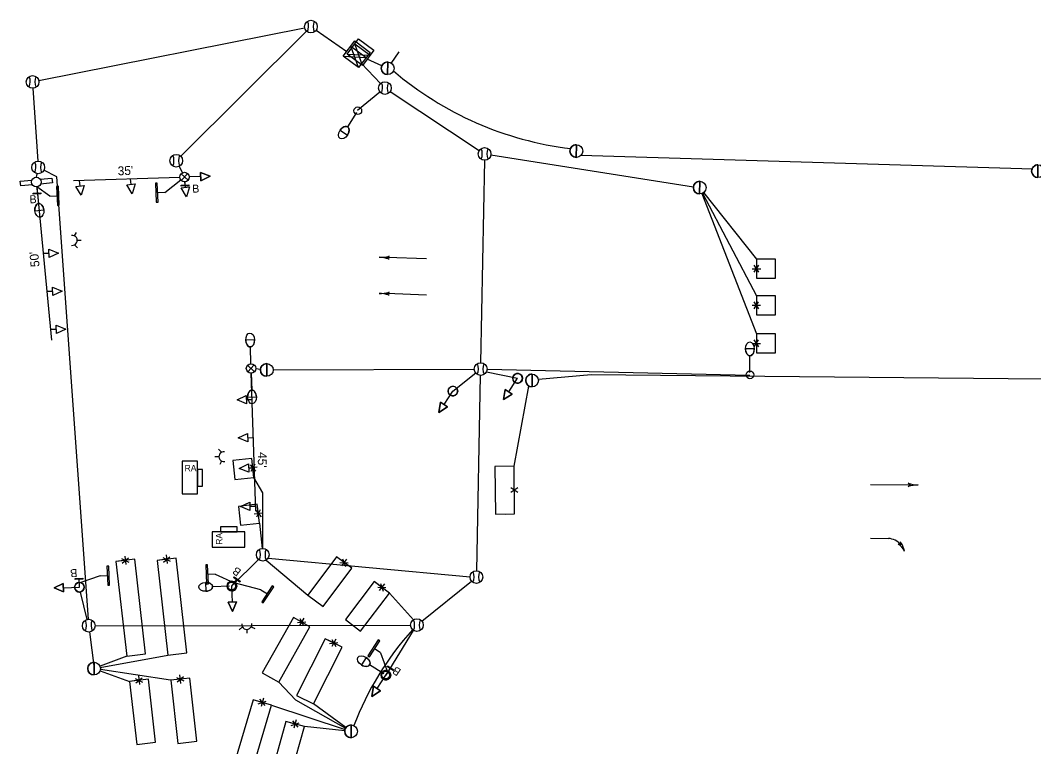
# Model space of a CAD drawing. Extents: x 596176 to 605330, y 332416 to 402398.
# Drawn here: x 604310.9 to 604629.8, y 339247.6 to 339476.3 of the extents above; entities that cross this region are included whole.
import ezdxf

# ---------------------------------------------------------------- set-up
doc = ezdxf.new("R2010")
doc.units = 0
for name, color, linetype in [('P_LTG', 7, 'Continuous'), ('P_SIG', 7, 'Continuous'), ('P_SIG_Bold', 7, 'Continuous'), ('P_SIG_Conduit', 7, 'Continuous'), ('P_SIG_IC', 7, 'Continuous'), ('P_SIG_Loops', 7, 'Continuous')]:
    doc.layers.add(name, color=color, linetype=linetype)

# ---------------------------------------------------------------- blocks, each defined once
blk = doc.blocks.new('_U321')
at = {"layer": 'P_LTG'}
for p, q in [((4.32, 25.12), (-4.14, 25.12)), ((0.05, 2.3), (0.05, 18.44))]:
    blk.add_line(p, q, dxfattribs=at)
blk.add_circle((0.05, 0.15), 3.68, dxfattribs=at)
blk.add_ellipse((0.09, 25.12), major_axis=(0, 6.65), ratio=0.636439, dxfattribs=at)
blk.add_ellipse((0.09, 25.12), major_axis=(0, 6.65), ratio=0.636439, start_param=1.570796, end_param=4.712389, dxfattribs=at)
blk = doc.blocks.new('_U322')
at = {"layer": 'P_LTG'}
for p, q in [((4.32, 25.12), (-4.14, 25.12)), ((0.05, 2.3), (0.05, 18.44))]:
    blk.add_line(p, q, dxfattribs=at)
blk.add_ellipse((0.09, 25.12), major_axis=(0, 6.65), ratio=0.636439, dxfattribs=at)
blk.add_ellipse((0.09, 25.12), major_axis=(0, 6.65), ratio=0.636439, start_param=1.570796, end_param=4.712389, dxfattribs=at)
blk = doc.blocks.new('_U226')
at = {"layer": 'P_SIG'}
blk.add_line((0.03, 6.11), (-0.03, -6.09), dxfattribs=at)
blk.add_lwpolyline([(-0.03, -6.09), (0.03, 6.11)], dxfattribs=at)
blk.add_circle((0, 0.01), 6.1, dxfattribs=at)
for start, end in [(89.70079, 180), (180, 269.70079)]:
    blk.add_arc((0, 0.01), 6.1, start, end, dxfattribs=at)
blk = doc.blocks.new('_U307')
at = {"layer": 'P_SIG_Loops'}
for p, q in [((0, 0), (0, -0.229)), ((0.467, -0.23), (0.671, -0.23)), ((0.517, -0.313), (0.624, -0.147)), ((0.627, -0.312), (0.518, -0.146))]:
    blk.add_line(p, q, dxfattribs=at)
blk.add_lwpolyline([(0, -0.229), (1.143, -0.229), (1.143, 0.229), (0, 0.229)], close=True, dxfattribs=at)
blk = doc.blocks.new('_U319')
at = {"layer": 'P_SIG'}
for p, q in [((-0.675, 0.115), (-0.743, 0.129)), ((-0.725, 0.057), (-0.743, 0.129)), ((-0.017, -0.02), (-0.443, -0.02))]:
    blk.add_line(p, q, dxfattribs=at)
for centre, radius, start, end in [((-0.479, 0.454), 0.392, 205.2667, 239.9151), ((-0.377, 0.361), 0.462, 189.3153, 221.1715), ((-0.412, 0.421), 0.442, 221.4708, 266.0347)]:
    blk.add_arc(centre, radius, start, end, dxfattribs=at)
blk = doc.blocks.new('_U318')
at = {"layer": 'P_SIG'}
blk.add_line((-0.017, -0.02), (-0.975, -0.02), dxfattribs=at)
blk.add_lwpolyline([(-0.914, 0.018), (-0.975, -0.02), (-0.914, -0.058)], dxfattribs=at)
for centre, start, end in [((-1.158, 0.78), 270, 287.7623), ((-1.158, -0.819), 72.2377, 90)]:
    blk.add_arc(centre, 0.799, start, end, dxfattribs=at)
blk = doc.blocks.new('CONTROL CABINET_2')
at = {"layer": 'P_SIG'}
for p, q in [((-0.229, 0.305), (0.229, 0.305)), ((-0.229, -0.152), (-0.229, 0.305)), ((0.229, 0.305), (0.229, -0.152)), ((-0.229, 0.152), (0.229, 0.152)), ((-0.229, -0.152), (0.229, 0.152)), ((0.229, -0.152), (-0.229, 0.152)), ((0.229, -0.152), (-0.229, -0.152))]:
    blk.add_line(p, q, dxfattribs=at)

msp = doc.modelspace()

# ---------------------------------------------------------------- linework, layer by layer
at = {"layer": 'P_SIG'}
for p, q in [((604412.53, 339465.01), (604416.12, 339469.82)), ((604416.12, 339469.82), (604420.93, 339466.23)), ((604414.93, 339468.21), (604419.74, 339464.63)), ((604417.34, 339461.42), (604414.93, 339468.21)), ((604417.34, 339461.42), (604412.53, 339465.01)), ((604412.53, 339465.01), (604419.74, 339464.63)), ((604420.93, 339466.23), (604417.34, 339461.42)), ((604329.66, 339424.14), (604329.45, 339425.9)), ((604345.71, 339424.66), (604345.5, 339426.42)), ((604356.38, 339422.11), (604361.38, 339426.04)), ((604362.84, 339423.71), (604362.63, 339425.47)), ((604362.63, 339425.46), (604362.67, 339424.47)), ((604367.61, 339427.11), (604364.06, 339427.01)), ((604524.7, 339425.64), (604524.68, 339421.64)), ((604316.05, 339423.89), (604316.14, 339421.91)), ((604320.12, 339420.97), (604316.11, 339423.9)), ((604356.38, 339422.11), (604353.98, 339422)), ((604320.12, 339420.97), (604322.52, 339421.08)), ((604327.93, 339408.43), (604328.5, 339409.52)), ((604328.77, 339407.07), (604330, 339407.09)), ((604319.9, 339402.91), (604318.13, 339402.86)), ((604327.95, 339405.64), (604328.85, 339404.67)), ((604438.73, 339401.16), (604426.17, 339401.61)), ((604321.06, 339390.95), (604319.29, 339390.89)), ((604438.73, 339389.81), (604426.17, 339390.25)), ((604322.22, 339378.98), (604320.45, 339378.92)), ((604388.46, 339368.23), (604388.44, 339364.23)), ((604464.6, 339359.35), (604467.38, 339363.58)), ((604444.23, 339355.34), (604447.01, 339359.56)), ((604382.04, 339356.89), (604383.81, 339356.94)), ((604382.43, 339344.89), (604384.2, 339344.95)), ((604373.36, 339338.87), (604372.14, 339338.84)), ((604374.19, 339340.3), (604373.29, 339341.27)), ((604374.21, 339337.5), (604373.64, 339336.42)), ((604382.73, 339335.32), (604384.5, 339335.37)), ((604383.1, 339323.28), (604384.87, 339323.34)), ((604335.97, 339301.38), (604329.33, 339299.05)), ((604335.97, 339301.38), (604338.37, 339301.5)), ((604372.22, 339301.9), (604369.82, 339301.79)), ((604372.22, 339301.9), (604378.2, 339299.14)), ((604324.42, 339297.65), (604329.48, 339297.8)), ((604329.48, 339297.77), (604329.34, 339300.27)), ((604377.45, 339298.14), (604378.95, 339300.14)), ((604377.6, 339293.11), (604377.45, 339298.16)), ((604386.61, 339296.99), (604378.2, 339299.14)), ((604386.61, 339296.99), (604388.62, 339295.68)), ((604380.75, 339285.33), (604379.78, 339284.43)), ((604382.18, 339284.51), (604382.2, 339283.28)), ((604383.54, 339285.35), (604384.63, 339284.78)), ((604424.25, 339277.16), (604422.23, 339278.46)), ((604424.25, 339277.16), (604426.55, 339270.89)), ((604334.1, 339274.17), (604334.08, 339270.17)), ((604425.9, 339270.07), (604427.28, 339272.15)), ((604423.13, 339265.87), (604425.91, 339270.09)), ((604414.98, 339254.42), (604414.96, 339250.42))]:
    msp.add_line(p, q, dxfattribs=at)
for points in [[(604370.57, 339427.2), (604367.65, 339425.79), (604367.57, 339428.43), (604370.57, 339427.2)], [(604370.57, 339427.2), (604367.65, 339425.79), (604367.57, 339428.43), (604370.57, 339427.2)], [(604367.57, 339428.43), (604367.65, 339425.79), (604370.57, 339427.2), (604367.57, 339428.43)], [(604524.68, 339421.64), (604524.7, 339425.64)], [(604426.98, 339402.08), (604426.17, 339401.61), (604426.95, 339401.08)], [(604426.98, 339390.72), (604426.17, 339390.25), (604426.95, 339389.73)], [(604388.44, 339364.23), (604388.46, 339368.23)], [(604462.99, 339356.88), (604463.5, 339360.07), (604465.71, 339358.63), (604462.99, 339356.88)], [(604463.5, 339360.07), (604462.99, 339356.88), (604465.71, 339358.63), (604463.5, 339360.07)], [(604442.61, 339352.86), (604443.13, 339356.06), (604445.33, 339354.61), (604442.61, 339352.86)], [(604443.13, 339356.06), (604442.61, 339352.86), (604445.33, 339354.61), (604443.13, 339356.06)], [(604321.47, 339297.56), (604324.38, 339298.97), (604324.47, 339296.33), (604321.47, 339297.56)], [(604324.38, 339298.97), (604321.47, 339297.56), (604324.47, 339296.33), (604324.38, 339298.97)], [(604377.69, 339290.15), (604376.28, 339293.07), (604378.92, 339293.15), (604377.69, 339290.15)], [(604376.28, 339293.07), (604377.69, 339290.15), (604378.92, 339293.15), (604376.28, 339293.07)], [(604334.08, 339270.17), (604334.1, 339274.17)], [(604421.52, 339263.39), (604422.03, 339266.59), (604424.24, 339265.15), (604421.52, 339263.39)], [(604422.03, 339266.59), (604421.52, 339263.39), (604424.24, 339265.15), (604422.03, 339266.59)], [(604414.96, 339250.42), (604414.98, 339254.42)]]:
    msp.add_lwpolyline(points, dxfattribs=at)
for points in [[(604346.06, 339421.72), (604344.41, 339424.5), (604347.02, 339424.81)], [(604354.25, 339419.05), (604353.97, 339425.04), (604353.37, 339425.01), (604353.65, 339419.02)], [(604314.94, 339421.86), (604317.34, 339421.97), (604317.35, 339421.64), (604314.95, 339421.53)], [(604322.24, 339424.03), (604322.52, 339418.03), (604323.12, 339418.06), (604322.84, 339424.06)], [(604330.01, 339421.21), (604328.36, 339423.99), (604330.97, 339424.3)], [(604361.47, 339424.41), (604363.87, 339424.52), (604363.89, 339424.2), (604361.49, 339424.09)], [(604363.19, 339420.77), (604361.53, 339423.55), (604364.14, 339423.86)], [(604322.86, 339403.01), (604319.94, 339401.6), (604319.86, 339404.23)], [(604324.02, 339391.04), (604321.1, 339389.63), (604321.02, 339392.26)], [(604325.17, 339379.07), (604322.26, 339377.66), (604322.17, 339380.29)], [(604379.09, 339356.79), (604382, 339358.2), (604382.08, 339355.57)], [(604379.47, 339344.8), (604382.39, 339346.21), (604382.47, 339343.58)], [(604366.6, 339327.17), (604366.6, 339337.52), (604361.78, 339337.52), (604361.78, 339327.17)], [(604379.78, 339335.22), (604382.69, 339336.63), (604382.78, 339334)], [(604368.23, 339334.89), (604366.63, 339334.89), (604366.63, 339329.62), (604368.23, 339329.62)], [(604380.15, 339323.19), (604383.06, 339324.6), (604383.15, 339321.97)], [(604373.85, 339316.83), (604373.85, 339315.23), (604379.12, 339315.23), (604379.12, 339316.83)], [(604381.57, 339315.2), (604371.23, 339315.2), (604371.23, 339310.37), (604381.57, 339310.37)], [(604338.1, 339304.44), (604338.38, 339298.45), (604338.98, 339298.48), (604338.7, 339304.47)], [(604370.09, 339298.84), (604369.82, 339304.84), (604369.22, 339304.81), (604369.49, 339298.81)], [(604330.54, 339300.34), (604328.14, 339300.2), (604328.12, 339300.52), (604330.52, 339300.66)], [(604379.91, 339299.43), (604377.99, 339300.86), (604378.18, 339301.12), (604380.1, 339299.69)], [(604390.12, 339298.23), (604386.84, 339293.2), (604387.34, 339292.88), (604390.62, 339297.9)], [(604420.74, 339275.91), (604424, 339280.95), (604423.49, 339281.27), (604420.24, 339276.23)], [(604428.28, 339271.49), (604426.28, 339272.82), (604426.46, 339273.09), (604428.46, 339271.76)]]:
    msp.add_lwpolyline(points, close=True, dxfattribs=at)
for centre, radius in [((604402.31, 339474.34), 2), ((604314.71, 339456.92), 2), ((604425.6, 339454.98), 2), ((604456.98, 339434.26), 2), ((604316.49, 339430), 2), ((604359.94, 339432.11), 2), ((604524.69, 339423.64), 2), ((604388.45, 339366.23), 2), ((604455.76, 339366.51), 2), ((604467.38, 339363.58), 1.52), ((604467.38, 339363.58), 1.52), ((604467.38, 339363.58), 1.52), ((604447.01, 339359.56), 1.52), ((604447.01, 339359.56), 1.52), ((604447.01, 339359.56), 1.52), ((604387.17, 339308.02), 2), ((604454.4, 339301), 2), ((604329.48, 339297.8), 1.52), ((604329.48, 339297.8), 1.52), ((604329.48, 339297.8), 1.52), ((604377.45, 339298.16), 1.52), ((604377.45, 339298.16), 1.52), ((604377.45, 339298.16), 1.52), ((604332.42, 339285.69), 2), ((604435.69, 339285.86), 2), ((604334.09, 339272.17), 2), ((604425.91, 339270.09), 1.52), ((604425.91, 339270.09), 1.52), ((604425.91, 339270.09), 1.52), ((604414.97, 339252.42), 2)]:
    msp.add_circle(centre, radius, dxfattribs=at)
for centre, radius, start, end in [((604397.24, 339474.37), 4.36, 336.6741, 22.5272), ((604407.38, 339474.38), 4.36, 157.5751, 203.4282), ((604309.64, 339456.95), 4.36, 336.6741, 22.5272), ((604319.78, 339456.96), 4.36, 157.5751, 203.4282), ((604420.53, 339455.01), 4.36, 336.6741, 22.5272), ((604430.67, 339455.02), 4.36, 157.5751, 203.4282), ((604451.91, 339434.29), 4.36, 336.6741, 22.5272), ((604462.05, 339434.3), 4.36, 157.5751, 203.4282), ((604311.42, 339430.03), 4.36, 336.6741, 22.5272), ((604321.56, 339430.04), 4.36, 157.5751, 203.4282), ((604354.87, 339432.14), 4.36, 336.6741, 22.5272), ((604365.01, 339432.15), 4.36, 157.5751, 203.4282), ((604524.69, 339423.64), 2, 89.7008, 180), ((604524.69, 339423.64), 2, 180, 269.7008), ((604327.2, 339407.03), 1.58, 263.3712, 98.8787), ((604424.14, 339412.17), 10.49, 267.9585, 285.7208), ((604423.39, 339391.21), 10.49, 70.1962, 87.9585), ((604424.14, 339400.82), 10.49, 267.9585, 285.7208), ((604423.39, 339379.86), 10.49, 70.1962, 87.9585), ((604388.45, 339366.23), 2, 89.7008, 180), ((604450.69, 339366.54), 4.36, 336.6741, 22.5272), ((604460.83, 339366.55), 4.36, 157.5751, 203.4282), ((604388.45, 339366.23), 2, 180, 269.7008), ((604467.38, 339363.58), 1.52, 56.8293, 236.8293), ((604467.38, 339363.58), 1.52, 236.8293, 56.8293), ((604447.01, 339359.56), 1.52, 56.8293, 236.8293), ((604447.01, 339359.56), 1.52, 236.8293, 56.8293), ((604374.94, 339338.91), 1.58, 83.3712, 278.8787), ((604382.1, 339308.06), 4.36, 336.6741, 22.5272), ((604392.24, 339308.07), 4.36, 157.5751, 203.4282), ((604449.33, 339301.04), 4.36, 336.6741, 22.5272), ((604459.47, 339301.05), 4.36, 157.5751, 203.4282), ((604329.48, 339297.8), 1.52, 1.8031, 181.8031), ((604329.48, 339297.8), 1.52, 181.8031, 1.8031), ((604377.45, 339298.16), 1.52, 91.8031, 271.8031), ((604377.45, 339298.16), 1.52, 271.8031, 91.8031), ((604327.35, 339285.73), 4.36, 336.6741, 22.5272), ((604337.49, 339285.73), 4.36, 157.5751, 203.4282), ((604382.14, 339286.08), 1.58, 173.3712, 8.8787), ((604430.62, 339285.9), 4.36, 336.6741, 22.5272), ((604440.76, 339285.9), 4.36, 157.5751, 203.4282), ((604334.09, 339272.17), 2, 89.7008, 180), ((604334.09, 339272.17), 2, 180, 269.7008), ((604425.91, 339270.09), 1.52, 56.8293, 236.8293), ((604425.91, 339270.09), 1.52, 236.8293, 56.8293), ((604414.97, 339252.42), 2, 89.7008, 180), ((604414.97, 339252.42), 2, 180, 269.7008)]:
    msp.add_arc(centre, radius, start, end, dxfattribs=at)
at = {"layer": 'P_SIG_Bold'}
for p, q in [((604363.58, 339428.06), (604361.53, 339425.87)), ((604327.58, 339425.84), (604361.06, 339426.92)), ((604361.46, 339427.99), (604363.65, 339425.94)), ((604316.05, 339423.89), (604320.71, 339375.62)), ((604382.4, 339367.72), (604384.59, 339365.66)), ((604382.47, 339365.6), (604384.52, 339367.78)), ((604384.94, 339321.71), (604383.55, 339365.19))]:
    msp.add_line(p, q, dxfattribs=at)
for points in [[(604314.68, 339424.51), (604311, 339424.16), (604310.85, 339425.65), (604314.54, 339426.01)], [(604317.12, 339426.26), (604320.81, 339426.61), (604320.95, 339425.12), (604317.27, 339424.76)]]:
    msp.add_lwpolyline(points, dxfattribs=at)
for centre in [(604362.56, 339426.96), (604315.9, 339425.39), (604383.5, 339366.69)]:
    msp.add_circle(centre, 1.5, dxfattribs=at)
at = {"layer": 'P_SIG_Conduit'}
for p, q in [((604316.66, 339457.36), (604400.34, 339473.95)), ((604361.35, 339433.52), (604400.89, 339472.93)), ((604403.95, 339473.2), (604413.66, 339466.52)), ((604314.84, 339454.92), (604316.36, 339431.99)), ((604424.05, 339453.71), (604416.97, 339447.87)), ((604427.27, 339453.88), (604455.31, 339435.36)), ((604456.94, 339432.26), (604455.71, 339368.51)), ((604316, 339426.88), (604316.17, 339428.02)), ((604360.84, 339430.33), (604361.88, 339428.3)), ((604455.63, 339364.51), (604454.44, 339303)), ((604457.76, 339366.47), (604540.44, 339364.59)), ((604377.45, 339298.19), (604385.87, 339306.5)), ((604437.26, 339287.1), (604452.84, 339299.74)), ((604329.66, 339296.29), (604331.85, 339287.61)), ((604334.42, 339285.68), (604433.69, 339285.83)), ((604332.67, 339283.71), (604334.09, 339272.17))]:
    msp.add_line(p, q, dxfattribs=at)
for points in [[(604418.3, 339462.7), (604424.22, 339456.43)], [(604458.96, 339433.95), (604522.77, 339423.92)], [(604332.28, 339287.69), (604322.39, 339427.06), (604318.27, 339429.09)], [(604386.46, 339366.41), (604384.99, 339366.55)], [(604390.45, 339366.23), (604453.76, 339366.5)], [(604447.01, 339359.56), (604454.2, 339365.26)], [(604457.57, 339365.64), (604467.38, 339363.58)], [(604632.71, 339363.27), (604490.54, 339364.68), (604473.91, 339363.18)], [(604388.85, 339306.94), (604452.4, 339301.03)], [(604425.97, 339270.06), (604434.61, 339284.18)]]:
    msp.add_lwpolyline(points, dxfattribs=at)
msp.add_arc((604504.2, 339220.92), 94.4, 137.747, 159.353, dxfattribs=at)
at = {"layer": 'P_SIG_IC'}
for points in [[(604429.97, 339466.41), (604427.45, 339462.73)], [(604424.64, 339462.02), (604420.01, 339464.05)], [(604629.49, 339429.46), (604487.32, 339433.76)]]:
    msp.add_lwpolyline(points, dxfattribs=at)
msp.add_arc((604496.64, 339540.36), 105.18, 229.479, 263.1167, dxfattribs=at)
at = {"layer": 'P_SIG_Loops'}
for p, q in [((604525.41, 339421.77), (604542.53, 339377.59)), ((604525.62, 339421.87), (604542.53, 339389.6)), ((604525.93, 339422.07), (604542.57, 339401.1)), ((604541.2, 339398.08), (604543.88, 339398.09)), ((604541.85, 339397), (604543.26, 339399.17)), ((604543.31, 339397.01), (604541.88, 339399.18)), ((604542.57, 339398.1), (604542.58, 339395.1)), ((604541.16, 339386.58), (604543.84, 339386.58)), ((604541.81, 339385.49), (604543.22, 339387.67)), ((604543.27, 339385.51), (604541.83, 339387.68)), ((604542.53, 339386.6), (604542.53, 339383.6)), ((604541.16, 339374.57), (604543.84, 339374.58)), ((604541.81, 339373.49), (604543.22, 339375.66)), ((604543.27, 339373.5), (604541.83, 339375.67)), ((604542.53, 339374.59), (604542.53, 339371.59)), ((604466.26, 339335.87), (604470.95, 339361.15)), ((604385.4, 339335.56), (604382.74, 339335.25)), ((604383.18, 339336.39), (604384.85, 339334.39)), ((604384.63, 339336.56), (604383.47, 339334.24)), ((604384.04, 339335.38), (604383.7, 339338.36)), ((604385.8, 339320.95), (604385.46, 339323.93)), ((604387.17, 339321.12), (604384.5, 339320.82)), ((604384.95, 339321.95), (604386.62, 339319.96)), ((604386.39, 339322.13), (604385.24, 339319.81)), ((604342.75, 339306.84), (604345.07, 339305.69)), ((604342.92, 339305.4), (604344.92, 339307.06)), ((604343.75, 339307.61), (604344.06, 339304.95)), ((604355.73, 339307.18), (604358.05, 339306.03)), ((604355.91, 339305.73), (604357.9, 339307.4)), ((604356.74, 339307.95), (604357.04, 339305.29)), ((604412.75, 339305.55), (604410.34, 339307.33)), ((604343.93, 339306.25), (604340.95, 339305.91)), ((604356.91, 339306.59), (604353.93, 339306.25)), ((604388.24, 339306.34), (604401.41, 339295.28)), ((604411.44, 339305.61), (604414.03, 339305.47)), ((604413.55, 339306.66), (604411.96, 339304.51)), ((604412.29, 339306.78), (604413.2, 339304.36)), ((604424.65, 339297.76), (604422.26, 339299.57)), ((604423.34, 339297.83), (604425.93, 339297.66)), ((604425.47, 339298.86), (604423.85, 339296.73)), ((604424.21, 339299), (604425.09, 339296.56)), ((604427.04, 339295.94), (604434.64, 339287.57)), ((604399.43, 339286.83), (604396.81, 339288.3)), ((604400.08, 339288.03), (604398.77, 339285.7)), ((604398.82, 339288), (604400.02, 339285.7)), ((604398.12, 339286.72), (604400.71, 339286.91)), ((604409.52, 339280.24), (604406.84, 339281.59)), ((604408.86, 339281.38), (604410.16, 339279.14)), ((604410.12, 339281.47), (604408.92, 339279.08)), ((604408.21, 339280.08), (604410.8, 339280.38)), ((604344.35, 339276.1), (604335.95, 339272.91)), ((604336.05, 339272.55), (604357.33, 339276.44)), ((604358.12, 339268.48), (604336.07, 339271.86)), ((604335.97, 339271.49), (604345.23, 339268.15)), ((604347.03, 339269.08), (604349.35, 339267.93)), ((604347.2, 339267.64), (604349.2, 339269.31)), ((604348.03, 339269.85), (604348.34, 339267.19)), ((604361.19, 339268.83), (604358.21, 339268.49)), ((604360.01, 339269.42), (604362.33, 339268.27)), ((604360.19, 339267.98), (604362.19, 339269.64)), ((604361.02, 339270.19), (604361.32, 339267.53)), ((604348.21, 339268.49), (604345.23, 339268.15)), ((604387.01, 339261.51), (604384.13, 339262.36)), ((604386.15, 339262.51), (604387.84, 339260.55)), ((604387.38, 339262.83), (604386.62, 339260.26)), ((604385.75, 339261.12), (604388.24, 339261.87)), ((604413.36, 339253.6), (604403.18, 339261.04)), ((604397.72, 339256.03), (604397, 339253.45)), ((604397.37, 339254.71), (604394.48, 339255.51)), ((604396.12, 339254.29), (604398.6, 339255.09)), ((604396.5, 339255.7), (604398.21, 339253.75)), ((604412.98, 339252.62), (604400.26, 339253.9))]:
    msp.add_line(p, q, dxfattribs=at)
for points in [[(604542.58, 339395.1), (604548.58, 339395.11), (604548.57, 339401.11), (604542.57, 339401.1)], [(604542.53, 339383.6), (604548.53, 339383.6), (604548.53, 339389.6), (604542.53, 339389.6)], [(604542.53, 339371.59), (604548.53, 339371.6), (604548.53, 339377.6), (604542.53, 339377.59)], [(604383.7, 339338.36), (604377.73, 339337.68), (604378.42, 339331.72), (604384.38, 339332.4)], [(604385.46, 339323.93), (604379.5, 339323.25), (604380.18, 339317.29), (604386.14, 339317.97)], [(604353.93, 339306.25), (604357.33, 339276.44), (604363.29, 339277.12), (604359.89, 339306.93)], [(604410.34, 339307.33), (604401.41, 339295.28), (604406.23, 339291.71), (604415.16, 339303.76)], [(604340.95, 339305.91), (604344.35, 339276.1), (604350.31, 339276.78), (604346.91, 339306.59)], [(604422.26, 339299.57), (604413.2, 339287.61), (604417.98, 339283.99), (604427.04, 339295.94)], [(604396.81, 339288.3), (604387.01, 339270.86), (604392.24, 339267.92), (604402.04, 339285.36)], [(604406.84, 339281.59), (604397.82, 339263.74), (604403.18, 339261.04), (604412.2, 339278.89)], [(604345.23, 339268.15), (604347.49, 339248.28), (604353.46, 339248.96), (604351.19, 339268.83)], [(604358.21, 339268.49), (604360.48, 339248.62), (604366.44, 339249.3), (604364.17, 339269.17)], [(604384.13, 339262.36), (604378.48, 339243.18), (604384.23, 339241.48), (604389.89, 339260.66)], [(604394.48, 339255.51), (604389.09, 339236.25), (604394.87, 339234.64), (604400.26, 339253.9)]]:
    msp.add_lwpolyline(points, close=True, dxfattribs=at)
for points in [[(604387.17, 339310.02), (604387.16, 339327.57), (604384.38, 339332.4)], [(604386.14, 339317.97), (604386.96, 339310.01)], [(604392.24, 339267.92), (604397.46, 339262.3), (604413.23, 339253.4)], [(604389.89, 339260.66), (604413.07, 339253.04)]]:
    msp.add_lwpolyline(points, dxfattribs=at)

# ---------------------------------------------------------------- block references
at = {"layer": 'P_SIG'}
for name, p, xscale, yscale, rotation in [('CONTROL CABINET_2', (604417.36, 339465.5), 13.123333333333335, 13.123333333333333, -36.610651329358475), ('_U321', (604417.13, 339447.88), 0.32808333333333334, 0.32808333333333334, 147.58059147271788), ('_U322', (604315.98, 339424.64), 0.32808333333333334, 0.32808333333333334, -173.71516295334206), ('_U322', (604383.46, 339367.43), 0.32808333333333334, 0.3280833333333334, 1.956191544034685), ('_U321', (604540.49, 339364.63), 0.3280833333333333, 0.32808333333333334, 0.28242094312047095), ('_U322', (604383.54, 339365.94), 0.3280833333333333, 0.32808333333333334, -178.0438084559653), ('_U318', (604578.27, 339329.91), 13.123333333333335, 13.123333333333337, 179.35577875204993), ('_U319', (604578.27, 339312.98), 13.123333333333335, 13.123333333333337, 179.35577875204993), ('_U321', (604377.45, 339298.16), 0.32808333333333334, 0.32808333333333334, 91.9352759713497), ('_U321', (604425.9, 339270.07), 0.3280833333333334, 0.32808333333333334, 57.58059147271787)]:
    msp.add_blockref(name, p, dxfattribs=dict(at, xscale=xscale, yscale=yscale, rotation=rotation))
at = {"layer": 'P_SIG_Conduit', "xscale": 0.32808333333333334, "yscale": 0.32808333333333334}
msp.add_blockref('_U226', (604471.93, 339362.89), dxfattribs=at)
at = {"layer": 'P_SIG_IC', "xscale": 0.32808333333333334, "yscale": 0.32808333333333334}
for p in [(604426.48, 339461.21), (604485.87, 339435.14), (604631.14, 339428.81)]:
    msp.add_blockref('_U226', p, dxfattribs=at)
at = {"layer": 'P_SIG_Loops', "xscale": 13.123333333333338, "yscale": 13.123333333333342, "rotation": 90.59788262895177}
msp.add_blockref('_U307', (604463.42, 339320.84), dxfattribs=at)

# ---------------------------------------------------------------- texts
at = {"layer": 'P_SIG'}
for s, height, rotation, p in [('B', 2.52, 2.6556, (604365.02, 339422.01)), ('B', 2.52, 2.6556, (604313.82, 339418.67)), ("50'", 2.8, 95.5203, (604316.95, 339398.75)), ('RA', 2, 360, (604362.59, 339334.33)), ('RA', 2, 90, (604374.42, 339311.19)), ('B', 2.52, 143.3114, (604380.61, 339303.07)), ('B', 2.52, 183.2956, (604328.73, 339303.56)), ('B', 2.52, 146.3763, (604430.92, 339271.75))]:
    msp.add_text(s, height=height, rotation=rotation, dxfattribs=at).set_placement(p)
at = {"layer": 'P_SIG_Bold'}
for s, rotation, p in [("35'", 1.8373, (604341.57, 339427.5)), ("45'", 270, (604385.63, 339340.36))]:
    msp.add_text(s, height=2.8, rotation=rotation, dxfattribs=at).set_placement(p)

doc.saveas('drawing.dxf')
